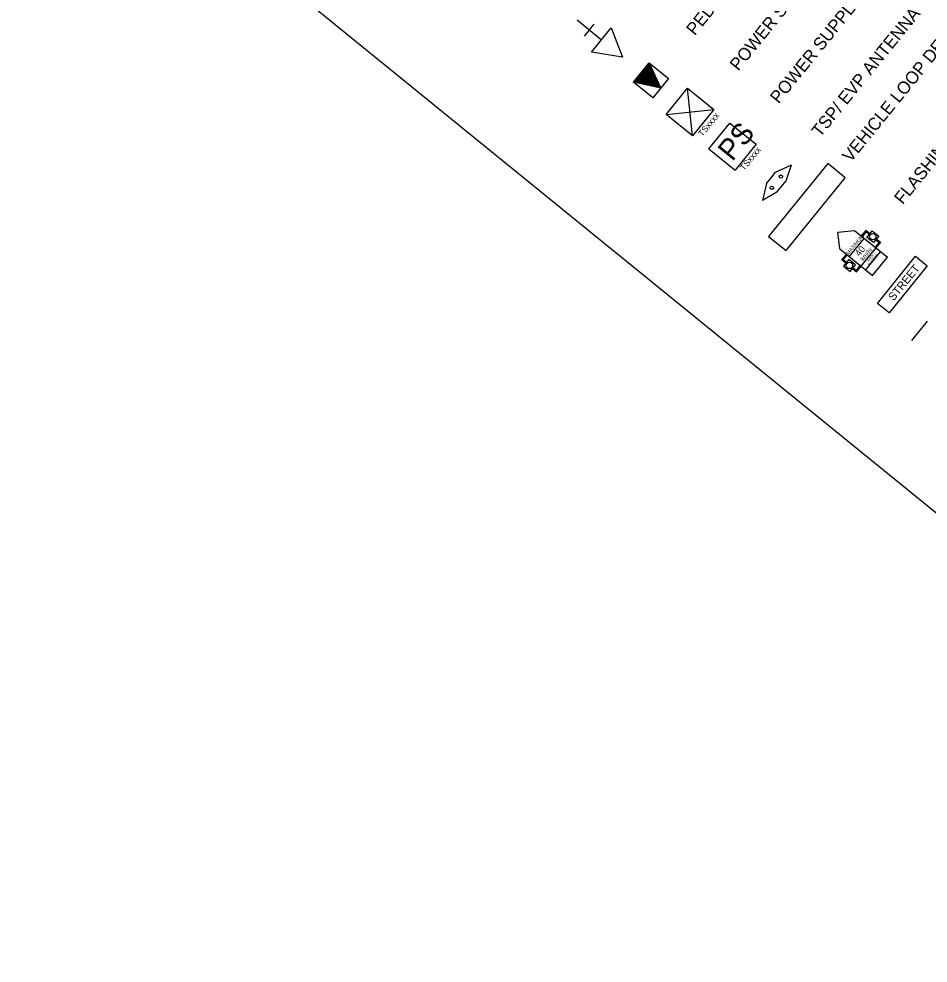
# Model space of a CAD drawing. Extents: x 592613 to 600223, y 4837996 to 4840103.
# Drawn here: x 592902.3 to 592933.8, y 4839229.51 to 4839262.21 of the extents above; entities that cross this region are included whole.
import ezdxf

# ---------------------------------------------------------------- set-up
doc = ezdxf.new("R2010")
doc.units = 0
for name, color, linetype in [('ENG_BORDER', 7, 'Continuous'), ('TCS_LEGEND', 7, 'Continuous'), ('TCS_LOOP', 7, 'Continuous'), ('TCS_POWER', 7, 'Continuous'), ('TCS_SIGN', 7, 'Continuous'), ('TCS_SIGNALHEAD', 7, 'Continuous'), ('TCS_TSP-EVP', 7, 'Continuous'), ('TCS_WR_12', 7, 'Continuous')]:
    doc.layers.add(name, color=color, linetype=linetype)

msp = doc.modelspace()

# ---------------------------------------------------------------- linework, layer by layer
at = {"layer": 'ENG_BORDER'}
msp.add_lwpolyline([(592902.303, 4839270.934), (593006.685, 4839186.123)], dxfattribs=at)
at = {"layer": 'TCS_LOOP'}
msp.add_lwpolyline([(592928.876, 4839254.186), (592930.927, 4839256.711), (592930.321, 4839257.204), (592928.27, 4839254.679)], close=True, dxfattribs=at)
at = {"layer": 'TCS_POWER'}
for p, q in [((592924.723, 4839258.902), (592925.462, 4839259.811)), ((592925.462, 4839259.811), (592926.371, 4839259.072)), ((592925.632, 4839258.163), (592925.462, 4839259.811)), ((592924.723, 4839258.902), (592926.371, 4839259.072)), ((592925.632, 4839258.163), (592924.723, 4839258.902)), ((592926.371, 4839259.072), (592925.632, 4839258.163)), ((592926.205, 4839257.708), (592926.933, 4839258.605)), ((592926.933, 4839258.605), (592927.84, 4839257.868)), ((592927.84, 4839257.868), (592927.111, 4839256.972)), ((592926.205, 4839257.708), (592927.112, 4839256.971))]:
    msp.add_line(p, q, dxfattribs=at)
at = {"layer": 'TCS_SIGN'}
for p, q in [((592930.668, 4839254.826), (592931.252, 4839254.88)), ((592930.734, 4839254.243), (592930.668, 4839254.826)), ((592931.067, 4839253.973), (592931.584, 4839254.61)), ((592931.252, 4839254.88), (592932.387, 4839253.958)), ((592931.639, 4839254.886), (592931.482, 4839254.693)), ((592931.645, 4839254.836), (592931.51, 4839254.67)), ((592931.782, 4839254.771), (592931.639, 4839254.886)), ((592931.759, 4839254.743), (592931.645, 4839254.836)), ((592932.006, 4839254.588), (592932.148, 4839254.473)), ((592931.471, 4839253.632), (592931.989, 4839254.268)), ((592932.097, 4839254.468), (592931.963, 4839254.302)), ((592931.983, 4839254.56), (592932.097, 4839254.468)), ((592932.148, 4839254.473), (592931.991, 4839254.28)), ((592930.734, 4839254.243), (592931.87, 4839253.321)), ((592930.808, 4839253.863), (592930.965, 4839254.056)), ((592930.858, 4839253.868), (592930.993, 4839254.033)), ((592931.633, 4839253.511), (592932.151, 4839254.147)), ((592931.87, 4839253.321), (592932.387, 4839253.958)), ((592930.95, 4839253.747), (592930.808, 4839253.863)), ((592930.973, 4839253.775), (592930.858, 4839253.868)), ((592931.311, 4839253.5), (592931.446, 4839253.665)), ((592931.317, 4839253.449), (592931.474, 4839253.642)), ((592931.174, 4839253.565), (592931.317, 4839253.449)), ((592931.197, 4839253.593), (592931.311, 4839253.5))]:
    msp.add_line(p, q, dxfattribs=at)
for points in [[(592932.086, 4839254.687), (592931.904, 4839254.462), (592931.679, 4839254.645), (592931.861, 4839254.869)], [(592932.039, 4839252.358), (592933.365, 4839253.99), (592933.769, 4839253.661), (592932.443, 4839252.029)], [(592931.095, 4839253.467), (592931.277, 4839253.691), (592931.053, 4839253.874), (592930.87, 4839253.649)]]:
    msp.add_lwpolyline(points, close=True, dxfattribs=at)
for centre in [(592931.88, 4839254.668), (592931.071, 4839253.672)]:
    msp.add_circle(centre, 0.111, dxfattribs=at)
at = {"layer": 'TCS_SIGNALHEAD'}
for p, q in [((592922.48, 4839261.479), (592921.636, 4839262.165)), ((592922.058, 4839261.822), (592921.887, 4839261.611)), ((592922.058, 4839261.822), (592922.23, 4839262.033)), ((592922.137, 4839261.056), (592922.823, 4839261.901)), ((592922.823, 4839261.901), (592923.211, 4839260.885)), ((592923.211, 4839260.885), (592922.137, 4839261.056)), ((592924.01, 4839259.927), (592923.954, 4839260.472)), ((592924.025, 4839259.923), (592923.967, 4839260.488)), ((592924.04, 4839259.92), (592923.98, 4839260.504)), ((592924.055, 4839259.917), (592923.993, 4839260.52)), ((592924.07, 4839259.913), (592924.006, 4839260.536)), ((592924.085, 4839259.91), (592924.018, 4839260.552)), ((592924.1, 4839259.907), (592924.031, 4839260.568)), ((592924.115, 4839259.903), (592924.044, 4839260.584)), ((592924.13, 4839259.9), (592924.057, 4839260.599)), ((592924.144, 4839259.897), (592924.07, 4839260.615)), ((592924.159, 4839259.893), (592924.083, 4839260.631)), ((592924.174, 4839259.89), (592924.096, 4839260.647)), ((592924.189, 4839259.887), (592924.109, 4839260.663)), ((592924.204, 4839259.884), (592924.122, 4839260.679)), ((592924.134, 4839260.694), (592924.807, 4839260.147)), ((592924.219, 4839259.88), (592924.135, 4839260.692)), ((592924.234, 4839259.877), (592924.154, 4839260.65)), ((592924.249, 4839259.874), (592924.172, 4839260.609)), ((592924.263, 4839259.87), (592924.191, 4839260.567)), ((592924.278, 4839259.867), (592924.21, 4839260.525)), ((592924.293, 4839259.864), (592924.229, 4839260.484)), ((592923.698, 4839259.996), (592923.683, 4839260.139)), ((592923.713, 4839259.993), (592923.696, 4839260.155)), ((592923.728, 4839259.989), (592923.709, 4839260.171)), ((592923.743, 4839259.986), (592923.722, 4839260.187)), ((592923.758, 4839259.983), (592923.735, 4839260.203)), ((592923.772, 4839259.979), (592923.748, 4839260.219)), ((592923.787, 4839259.976), (592923.761, 4839260.234)), ((592923.802, 4839259.973), (592923.774, 4839260.25)), ((592923.817, 4839259.969), (592923.786, 4839260.266)), ((592923.832, 4839259.966), (592923.799, 4839260.282)), ((592923.847, 4839259.963), (592923.812, 4839260.298)), ((592923.862, 4839259.96), (592923.825, 4839260.314)), ((592923.877, 4839259.956), (592923.838, 4839260.33)), ((592923.891, 4839259.953), (592923.851, 4839260.346)), ((592923.906, 4839259.95), (592923.864, 4839260.361)), ((592923.921, 4839259.946), (592923.877, 4839260.377)), ((592923.936, 4839259.943), (592923.89, 4839260.393)), ((592923.951, 4839259.94), (592923.902, 4839260.409)), ((592923.966, 4839259.936), (592923.915, 4839260.425)), ((592923.981, 4839259.933), (592923.928, 4839260.441)), ((592923.996, 4839259.93), (592923.941, 4839260.457)), ((592924.308, 4839259.86), (592924.248, 4839260.442)), ((592924.807, 4839260.147), (592924.26, 4839259.474)), ((592924.323, 4839259.857), (592924.267, 4839260.4)), ((592924.338, 4839259.854), (592924.286, 4839260.359)), ((592924.353, 4839259.85), (592924.304, 4839260.317)), ((592924.368, 4839259.847), (592924.323, 4839260.275)), ((592924.382, 4839259.844), (592924.342, 4839260.234)), ((592924.397, 4839259.841), (592924.361, 4839260.192)), ((592924.412, 4839259.837), (592924.38, 4839260.15)), ((592924.26, 4839259.474), (592923.587, 4839260.021)), ((592923.594, 4839260.019), (592923.593, 4839260.028)), ((592923.609, 4839260.016), (592923.606, 4839260.044)), ((592923.624, 4839260.012), (592923.619, 4839260.06)), ((592923.639, 4839260.009), (592923.632, 4839260.076)), ((592923.653, 4839260.006), (592923.645, 4839260.092)), ((592923.668, 4839260.003), (592923.657, 4839260.107)), ((592923.683, 4839259.999), (592923.67, 4839260.123)), ((592924.427, 4839259.834), (592924.399, 4839260.109)), ((592924.442, 4839259.831), (592924.417, 4839260.067)), ((592924.457, 4839259.827), (592924.436, 4839260.025)), ((592924.472, 4839259.824), (592924.455, 4839259.984)), ((592924.487, 4839259.821), (592924.474, 4839259.942)), ((592924.501, 4839259.817), (592924.493, 4839259.901)), ((592924.516, 4839259.814), (592924.512, 4839259.859)), ((592924.531, 4839259.811), (592924.531, 4839259.817))]:
    msp.add_line(p, q, dxfattribs=at)
for points in [[(592922.137, 4839261.056), (592922.823, 4839261.901), (592923.211, 4839260.885), (592923.211, 4839260.885)], [(592923.587, 4839260.021), (592924.134, 4839260.694), (592924.534, 4839259.81), (592924.534, 4839259.81)]]:
    msp.add_lwpolyline(points, close=True, dxfattribs=at)
at = {"layer": 'TCS_TSP-EVP'}
for p, q in [((592928.356, 4839256.705), (592928.515, 4839256.9)), ((592928.515, 4839256.9), (592929.062, 4839257.154)), ((592928.879, 4839256.604), (592929.062, 4839257.154)), ((592928.197, 4839256.509), (592928.356, 4839256.705)), ((592928.562, 4839256.213), (592928.879, 4839256.604)), ((592928.197, 4839256.509), (592928.06, 4839255.922)), ((592928.562, 4839256.213), (592928.06, 4839255.922))]:
    msp.add_line(p, q, dxfattribs=at)
for centre in [(592928.697, 4839256.752), (592928.379, 4839256.361)]:
    msp.add_circle(centre, 0.0578, dxfattribs=at)
at = {"layer": 'TCS_WR_12'}
msp.add_line((592933.227, 4839251.07), (592933.774, 4839251.743), dxfattribs=at)

# ---------------------------------------------------------------- texts
at = {"layer": 'TCS_LEGEND'}
for s, p in [('PEDESTRIAN SIGNAL HEAD', (592925.716, 4839261.609)), ('POWER SUPPLY PEDESTAL', (592927.223, 4839260.384)), ('POWER SUPPLY (ON POLE)', (592928.621, 4839259.248)), ('VEHICLE LOOP DETECTOR', (592931.117, 4839257.22)), ('TSP/ EVP ANTENNA', (592930.057, 4839258.082)), ('FLASHING 40 KM/HR SIGN', (592932.917, 4839255.758))]:
    msp.add_text(s, height=0.43374, rotation=50.9061, dxfattribs=at).set_placement(p)
at = {"layer": 'TCS_POWER'}
for s, height, p in [('TSxxxx', 0.2169, (592925.979, 4839258.118)), ('PS', 0.7229, (592927.014, 4839257.249)), ('TSxxxx', 0.2169, (592927.425, 4839256.936))]:
    msp.add_text(s, height=height, rotation=50.9061, dxfattribs=at).set_placement(p)
at = {"layer": 'TCS_SIGN'}
for s, height, p in [('MAXIMUM', 0.1265, (592931.042, 4839254.025)), ('40', 0.2318, (592931.42, 4839253.966)), ('km/hr', 0.1511, (592931.553, 4839253.821)), ('WHEN ', 0.0703, (592931.728, 4839253.791)), ('FLASHING', 0.0703, (592931.753, 4839253.672)), ('STREET', 0.2773, (592932.603, 4839252.426))]:
    msp.add_text(s, height=height, rotation=50.9061, dxfattribs=at).set_placement(p)

doc.saveas('drawing.dxf')
